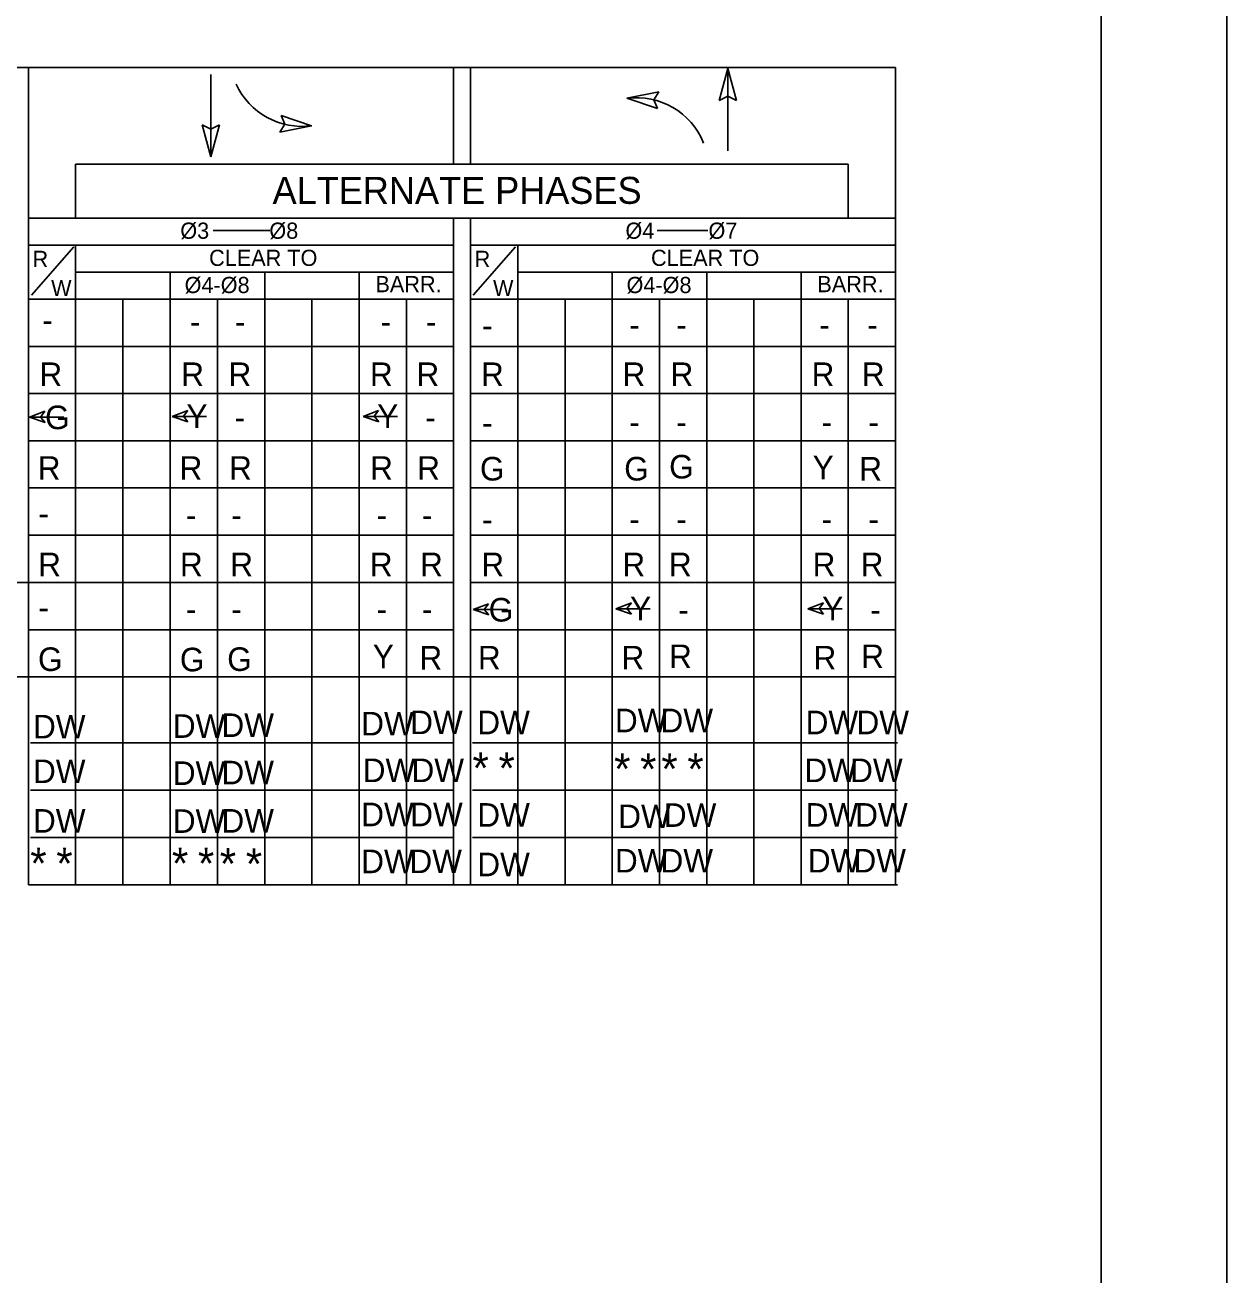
# Model space of a CAD drawing. Extents: x 0 to 3.01, y -0.05 to 1.83.
# Drawn here: x 2.6407 to 3, y 0.8925 to 1.2662 of the extents above; entities that cross this region are included whole.
import ezdxf

# ---------------------------------------------------------------- set-up
doc = ezdxf.new("R2010")
doc.units = 0
for name, color, linetype in [('RD_SHT_IplotShp', 7, 'Continuous'), ('TR_TS_Border', 7, 'Continuous'), ('TR_TS_Phase1', 7, 'Continuous'), ('TR_TS_Phase2', 7, 'Continuous'), ('TR_TS_Phase3', 7, 'Continuous'), ('TR_TS_Phase4', 7, 'Continuous'), ('TR_TS_Phase5', 7, 'Continuous'), ('TR_TS_Phase6', 7, 'Continuous'), ('TR_TS_Phase7', 7, 'Continuous'), ('TR_TS_Phase8', 7, 'Continuous')]:
    doc.layers.add(name, color=color, linetype=linetype)

msp = doc.modelspace()

# ---------------------------------------------------------------- linework, layer by layer
at = {"layer": 'RD_SHT_IplotShp'}
msp.add_lwpolyline([(-3.9736429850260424e-10, -8.265177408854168e-09), (3.0000020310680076, -8.265177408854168e-09), (3.0000020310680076, 1.8333311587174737), (-3.9736429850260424e-10, 1.8333311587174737)], close=True, dxfattribs=at)
at = {"layer": 'TR_TS_Border'}
for p, q in [((3.0000020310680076, -8.265177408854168e-09), (3.0000020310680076, 1.8333311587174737)), ((2.9623464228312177, 0.04746643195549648), (2.9623464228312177, 1.775395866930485)), ((2.900956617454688, 1.2534462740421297), (2.372526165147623, 1.2534462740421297)), ((2.6418031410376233, 1.009138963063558), (2.6418031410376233, 1.2534462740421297)), ((2.7688228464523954, 1.2534461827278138), (2.7688228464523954, 1.2245734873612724)), ((2.7738845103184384, 1.2534461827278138), (2.7738845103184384, 1.2245734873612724)), ((2.900956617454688, 1.2534462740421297), (2.900956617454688, 1.009138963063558)), ((2.886825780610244, 1.2245736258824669), (2.6558814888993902, 1.2245736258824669)), ((2.6558814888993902, 1.2245736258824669), (2.6558814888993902, 1.2084390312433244)), ((2.886825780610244, 1.2245736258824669), (2.886825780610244, 1.2084390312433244)), ((2.768822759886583, 1.2084390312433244), (2.6418031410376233, 1.2084390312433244)), ((2.768822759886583, 1.2084390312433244), (2.773884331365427, 1.2084390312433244)), ((2.7688228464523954, 1.2084389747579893), (2.7688228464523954, 1.0091388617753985)), ((2.900956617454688, 1.2084390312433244), (2.773884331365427, 1.2084390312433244)), ((2.7738845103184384, 1.2084389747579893), (2.7738845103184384, 1.0091388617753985)), ((2.696972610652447, 1.2046953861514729), (2.7138807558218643, 1.2046953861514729)), ((2.829719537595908, 1.2046953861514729), (2.844828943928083, 1.2046953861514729)), ((2.6418031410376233, 1.2003716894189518), (2.768822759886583, 1.2003716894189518)), ((2.6426469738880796, 1.185449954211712), (2.6553012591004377, 1.1998447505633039)), ((2.6558814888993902, 1.2003716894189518), (2.6558814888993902, 1.009138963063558)), ((2.773884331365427, 1.2003716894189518), (2.900956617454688, 1.2003716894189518)), ((2.774728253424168, 1.185449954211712), (2.787382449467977, 1.1998447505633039)), ((2.7880152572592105, 1.2003716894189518), (2.7880152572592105, 1.009138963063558)), ((2.6558814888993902, 1.192304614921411), (2.768822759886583, 1.192304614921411)), ((2.6841428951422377, 1.192304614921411), (2.6841428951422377, 1.009138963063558)), ((2.712404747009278, 1.192304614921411), (2.712404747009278, 1.009138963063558)), ((2.7406138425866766, 1.192304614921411), (2.7406138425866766, 1.009138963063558)), ((2.7880152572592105, 1.192304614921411), (2.900956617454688, 1.192304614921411)), ((2.8162241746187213, 1.192304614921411), (2.8162241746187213, 1.009138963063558)), ((2.8444860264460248, 1.192304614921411), (2.8444860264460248, 1.009138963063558)), ((2.872695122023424, 1.192304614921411), (2.872695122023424, 1.009138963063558)), ((2.768822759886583, 1.1842374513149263), (2.6418031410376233, 1.1842374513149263)), ((2.67001232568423, 1.1842374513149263), (2.67001232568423, 1.009138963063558)), ((2.6982737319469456, 1.1842374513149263), (2.6982737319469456, 1.009138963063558)), ((2.7264830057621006, 1.1842374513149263), (2.7264830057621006, 1.009138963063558)), ((2.7547445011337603, 1.1842374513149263), (2.7547445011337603, 1.009138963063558)), ((2.900956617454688, 1.1842374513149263), (2.773884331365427, 1.1842374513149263)), ((2.802146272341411, 1.1842374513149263), (2.802146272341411, 1.009138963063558)), ((2.8303550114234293, 1.1842374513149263), (2.8303550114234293, 1.009138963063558)), ((2.8586168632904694, 1.1842374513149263), (2.8586168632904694, 1.009138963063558)), ((2.886825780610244, 1.1842374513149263), (2.886825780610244, 1.009138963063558)), ((2.768822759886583, 1.1701066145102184), (2.6418031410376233, 1.1701066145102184)), ((2.900956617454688, 1.1701066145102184), (2.773884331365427, 1.1701066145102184)), ((2.768822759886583, 1.155975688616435), (2.6418031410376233, 1.155975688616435)), ((2.900956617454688, 1.155975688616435), (2.773884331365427, 1.155975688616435)), ((2.768822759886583, 1.1418975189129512), (2.6418031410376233, 1.1418975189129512)), ((2.900956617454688, 1.1418975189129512), (2.773884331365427, 1.1418975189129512)), ((2.768822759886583, 1.1277666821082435), (2.6418031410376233, 1.1277666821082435)), ((2.900956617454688, 1.1277666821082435), (2.773884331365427, 1.1277666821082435)), ((2.768822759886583, 1.113635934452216), (2.6418031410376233, 1.113635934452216)), ((2.900956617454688, 1.113635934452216), (2.773884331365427, 1.113635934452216)), ((2.6317323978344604, 1.099505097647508), (2.6418031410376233, 1.099505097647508)), ((2.768822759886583, 1.099505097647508), (2.6418031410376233, 1.099505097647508)), ((2.6418031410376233, 1.099505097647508), (2.6418031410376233, 1.0712960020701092)), ((2.900956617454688, 1.099505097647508), (2.773884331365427, 1.099505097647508)), ((2.768822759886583, 1.085374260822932), (2.6418031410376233, 1.085374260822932)), ((2.900956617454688, 1.085374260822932), (2.773884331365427, 1.085374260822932)), ((2.6418031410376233, 1.0712960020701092), (2.6317323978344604, 1.0712960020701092)), ((2.768822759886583, 1.0712960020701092), (2.6418031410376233, 1.0712960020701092)), ((2.768822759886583, 1.0712960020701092), (2.773884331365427, 1.0712960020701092)), ((2.900956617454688, 1.0712960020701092), (2.773884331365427, 1.0712960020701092)), ((2.768822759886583, 1.05153174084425), (2.6423805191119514, 1.05153174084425)), ((2.9015339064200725, 1.05153174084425), (2.774461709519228, 1.05153174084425)), ((2.768822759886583, 1.037400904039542), (2.6423805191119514, 1.037400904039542)), ((2.9015339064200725, 1.037400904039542), (2.774461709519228, 1.037400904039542)), ((2.768822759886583, 1.0232697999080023), (2.6423805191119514, 1.0232697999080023)), ((2.9015339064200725, 1.0232697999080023), (2.774461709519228, 1.0232697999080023)), ((2.7694001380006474, 1.009138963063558), (2.6418031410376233, 1.009138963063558)), ((2.7694001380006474, 1.009138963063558), (2.774461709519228, 1.009138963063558)), ((2.9015339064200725, 1.009138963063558), (2.774461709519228, 1.009138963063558))]:
    msp.add_line(p, q, dxfattribs=at)
at = {"layer": 'TR_TS_Phase3'}
for p, q in [((2.718364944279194, 1.2365514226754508), (2.717261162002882, 1.2391357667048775)), ((2.717261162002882, 1.2391357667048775), (2.7264059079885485, 1.2359971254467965)), ((2.7168954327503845, 1.2341504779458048), (2.718364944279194, 1.2365514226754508)), ((2.7264059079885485, 1.2359971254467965), (2.7168954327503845, 1.2341504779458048)), ((2.642075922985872, 1.1489186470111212), (2.6467103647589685, 1.1506814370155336)), ((2.652337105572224, 1.1489186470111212), (2.642075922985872, 1.1489186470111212)), ((2.646754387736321, 1.147310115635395), (2.642075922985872, 1.1489186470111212)), ((2.6467103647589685, 1.1506814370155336), (2.6453810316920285, 1.1489773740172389)), ((2.6453810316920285, 1.1489773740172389), (2.646754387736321, 1.147310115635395)), ((2.6847727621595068, 1.149179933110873), (2.689407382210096, 1.1509425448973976)), ((2.6950340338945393, 1.149179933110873), (2.6847727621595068, 1.149179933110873)), ((2.68945140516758, 1.1475714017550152), (2.6847727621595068, 1.149179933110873)), ((2.689407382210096, 1.1509425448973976), (2.6880778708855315, 1.1492386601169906)), ((2.6880778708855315, 1.1492386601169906), (2.68945140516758, 1.1475714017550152)), ((2.74178080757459, 1.149179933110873), (2.7464152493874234, 1.1509425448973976)), ((2.7520419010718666, 1.149179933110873), (2.74178080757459, 1.149179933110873)), ((2.7464594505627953, 1.1475714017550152), (2.74178080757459, 1.149179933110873)), ((2.7464152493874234, 1.1509425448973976), (2.74508591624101, 1.1492386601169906)), ((2.74508591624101, 1.1492386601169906), (2.7464594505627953, 1.1475714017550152))]:
    msp.add_line(p, q, dxfattribs=at)
msp.add_arc((2.7235502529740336, 1.2574811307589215), 0.021617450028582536, 204.5246166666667, 277.6927888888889, dxfattribs=at)
at = {"layer": 'TR_TS_Phase4'}
for p, q in [((2.850787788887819, 1.253204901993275), (2.8481964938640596, 1.2435802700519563)), ((2.850787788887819, 1.253204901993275), (2.850787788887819, 1.228584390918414)), ((2.8533789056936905, 1.2435802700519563), (2.850787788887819, 1.253204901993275)), ((2.8481964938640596, 1.2435802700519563), (2.850787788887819, 1.2449129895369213)), ((2.850787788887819, 1.2449129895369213), (2.8533789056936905, 1.2435802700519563))]:
    msp.add_line(p, q, dxfattribs=at)
at = {"layer": 'TR_TS_Phase7'}
for p, q in [((2.820663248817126, 1.2443299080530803), (2.830173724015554, 1.2461762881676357)), ((2.830173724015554, 1.2461762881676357), (2.8287042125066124, 1.243775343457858)), ((2.8298079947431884, 1.2411911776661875), (2.820663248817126, 1.2443299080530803)), ((2.8287042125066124, 1.243775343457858), (2.8298079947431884, 1.2411911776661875)), ((2.774661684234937, 1.0914069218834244), (2.7792963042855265, 1.0931695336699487)), ((2.784923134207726, 1.0914069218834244), (2.774661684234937, 1.0914069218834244)), ((2.7793403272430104, 1.08979839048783), (2.774661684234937, 1.0914069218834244)), ((2.7792963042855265, 1.0931695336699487), (2.777966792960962, 1.0914656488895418)), ((2.777966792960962, 1.0914656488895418), (2.7793403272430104, 1.08979839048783)), ((2.817358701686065, 1.091667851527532), (2.8219933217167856, 1.0934304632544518)), ((2.8276199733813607, 1.091667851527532), (2.817358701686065, 1.091667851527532)), ((2.822037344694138, 1.0900593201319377), (2.817358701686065, 1.091667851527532)), ((2.8219933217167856, 1.0934304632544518), (2.820663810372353, 1.0917265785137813)), ((2.820663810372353, 1.0917265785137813), (2.822037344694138, 1.0900593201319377)), ((2.87476687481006, 1.091667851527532), (2.8794014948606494, 1.0934304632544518)), ((2.8850279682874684, 1.091667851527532), (2.87476687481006, 1.091667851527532)), ((2.8794455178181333, 1.0900593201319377), (2.87476687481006, 1.091667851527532)), ((2.8794014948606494, 1.0934304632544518), (2.878071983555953, 1.0917265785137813)), ((2.878071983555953, 1.0917265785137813), (2.8794455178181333, 1.0900593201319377))]:
    msp.add_line(p, q, dxfattribs=at)
msp.add_arc((2.823518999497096, 1.2228452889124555), 0.021617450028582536, 21.869405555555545, 97.69278888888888, dxfattribs=at)
at = {"layer": 'TR_TS_Phase8'}
for p, q in [((2.6962813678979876, 1.2267372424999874), (2.6962813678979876, 1.2513575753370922)), ((2.6962813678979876, 1.2350288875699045), (2.693690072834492, 1.2363616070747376)), ((2.693690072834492, 1.2363616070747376), (2.6962813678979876, 1.2267372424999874)), ((2.698872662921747, 1.2363616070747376), (2.6962813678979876, 1.2350288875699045)), ((2.6962813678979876, 1.2267372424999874), (2.698872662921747, 1.2363616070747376))]:
    msp.add_line(p, q, dxfattribs=at)

# ---------------------------------------------------------------- texts
at = {"layer": 'TR_TS_Border'}
for s, height, p in [('ALTERNATE PHASES', 0.00806692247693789, (2.7147410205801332, 1.212709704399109)), ('Ø3          Ø8', 0.004840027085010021, (2.687162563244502, 1.202269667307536)), ('Ø4         Ø7', 0.004840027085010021, (2.820207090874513, 1.202269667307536)), ('R', 0.004840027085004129, (2.6430010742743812, 1.1938336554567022)), ('CLEAR TO', 0.004840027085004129, (2.6957715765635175, 1.1941499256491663)), ('R', 0.004840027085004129, (2.7751351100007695, 1.1938336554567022)), ('CLEAR TO', 0.004840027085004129, (2.827852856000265, 1.1941499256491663)), ('W', 0.004840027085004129, (2.6485480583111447, 1.1851340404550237)), ('Ø4-Ø8', 0.004840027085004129, (2.688454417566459, 1.186030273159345)), ('BARR.', 0.004840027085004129, (2.745489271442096, 1.186293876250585)), ('W', 0.004840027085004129, (2.780629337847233, 1.1851340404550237)), ('Ø4-Ø8', 0.004840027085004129, (2.82053560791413, 1.186030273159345)), ('BARR.', 0.004840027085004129, (2.877570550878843, 1.186293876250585))]:
    msp.add_text(s, height=height, rotation=360, dxfattribs=at).set_placement(p)
at = {"layer": 'TR_TS_Phase1'}
for p in [(2.645924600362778, 1.1744686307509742), (2.6900332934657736, 1.1739495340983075), (2.7035251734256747, 1.1739495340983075), (2.7470411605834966, 1.1739495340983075), (2.76053321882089, 1.1739495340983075), (2.7773641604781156, 1.172916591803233), (2.821382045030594, 1.1730729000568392), (2.835416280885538, 1.1730729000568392), (2.8781681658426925, 1.1730729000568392), (2.8925133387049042, 1.1730729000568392)]:
    msp.add_text('-', height=0.007050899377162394, dxfattribs=at).set_placement(p)
at = {"layer": 'TR_TS_Phase2'}
for p in [(2.64505608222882, 1.1582365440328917), (2.6874429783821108, 1.1582365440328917), (2.7015719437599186, 1.1582365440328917), (2.743845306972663, 1.1582365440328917), (2.757749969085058, 1.1582365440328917), (2.7770371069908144, 1.1582365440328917), (2.8193315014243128, 1.1582365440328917), (2.8336848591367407, 1.1582365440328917), (2.875847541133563, 1.1582365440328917), (2.890873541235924, 1.1582365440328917)]:
    msp.add_text('R', height=0.007050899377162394, rotation=360, dxfattribs=at).set_placement(p)
for p in [(2.8170630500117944, 1.0547270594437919), (2.8306928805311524, 1.0547270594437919), (2.6431330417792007, 1.052876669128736), (2.6849198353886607, 1.053052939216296), (2.6994478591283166, 1.0533047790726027), (2.741234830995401, 1.0537693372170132), (2.7558768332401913, 1.0541542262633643), (2.775932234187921, 1.0541259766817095), (2.874065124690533, 1.0541259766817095), (2.889252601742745, 1.0541259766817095)]:
    msp.add_text('DW', height=0.007050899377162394, dxfattribs=at).set_placement(p)
at = {"layer": 'TR_TS_Phase3'}
for s, p in [('G', (2.646752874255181, 1.145338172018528)), ('Y', (2.689002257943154, 1.1456915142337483)), ('Y', (2.7460103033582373, 1.1456915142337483)), ('-', (2.703372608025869, 1.145338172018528)), ('-', (2.760380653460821, 1.145338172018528)), ('-', (2.7773641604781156, 1.1437956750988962)), ('-', (2.821382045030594, 1.1439520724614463)), ('-', (2.835416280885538, 1.1439520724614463)), ('-', (2.87879021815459, 1.1439520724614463)), ('-', (2.892824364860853, 1.1439520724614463))]:
    msp.add_text(s, height=0.007050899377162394, dxfattribs=at).set_placement(p)
at = {"layer": 'TR_TS_Phase4'}
for s, height, p in [('R', 0.007050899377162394, (2.6445564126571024, 1.1302016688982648)), ('R', 0.007050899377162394, (2.6869433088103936, 1.1302016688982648)), ('R', 0.007050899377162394, (2.701745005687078, 1.1302016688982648)), ('R', 0.007050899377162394, (2.7439077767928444, 1.1302016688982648)), ('R', 0.007050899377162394, (2.7579548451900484, 1.1302016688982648)), ('G', 0.007050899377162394, (2.7767327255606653, 1.1299915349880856)), ('G', 0.007050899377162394, (2.8198378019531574, 1.1299915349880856)), ('G', 0.007050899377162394, (2.8332705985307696, 1.1305931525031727)), ('DW', 0.007050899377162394, (2.6431330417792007, 1.0395282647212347)), ('DW', 0.007050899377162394, (2.7416840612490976, 1.0398178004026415)), ('DW', 0.007050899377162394, (2.756261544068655, 1.0398178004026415)), ('*', 0.009384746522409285, (2.7744891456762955, 1.0393489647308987)), ('*', 0.009384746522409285, (2.7822597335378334, 1.0392927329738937)), ('*', 0.009384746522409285, (2.8168236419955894, 1.0390825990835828)), ('*', 0.009384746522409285, (2.8245942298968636, 1.0390261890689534)), ('*', 0.009384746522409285, (2.8309352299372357, 1.0390825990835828)), ('*', 0.009384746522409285, (2.8387058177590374, 1.0390261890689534)), ('DW', 0.007050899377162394, (2.873688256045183, 1.0398178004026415)), ('DW', 0.007050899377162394, (2.8873687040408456, 1.0398178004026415)), ('DW', 0.007050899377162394, (2.6849198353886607, 1.03896710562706)), ('DW', 0.007050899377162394, (2.6994478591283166, 1.0391546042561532))]:
    msp.add_text(s, height=height, dxfattribs=at).set_placement(p)
for s, p in [('Y', (2.876168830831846, 1.130357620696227)), ('R', (2.890087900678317, 1.1299839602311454))]:
    msp.add_text(s, height=0.007050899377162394, rotation=360, dxfattribs=at).set_placement(p)
at = {"layer": 'TR_TS_Phase5'}
for p in [(2.644754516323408, 1.116682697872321), (2.688863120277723, 1.116163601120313), (2.7023550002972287, 1.116163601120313), (2.745870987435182, 1.116163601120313), (2.7593630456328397, 1.116163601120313), (2.7773641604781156, 1.11482651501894), (2.821382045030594, 1.114982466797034), (2.835416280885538, 1.114982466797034), (2.87879021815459, 1.114982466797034), (2.892824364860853, 1.114982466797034)]:
    msp.add_text('-', height=0.007050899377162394, dxfattribs=at).set_placement(p)
at = {"layer": 'TR_TS_Phase6'}
for s, p in [('R', (2.6446761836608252, 1.1013816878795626)), ('R', (2.6870629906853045, 1.1013816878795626)), ('R', (2.7020890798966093, 1.1013816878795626)), ('R', (2.7438031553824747, 1.1013816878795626)), ('R', (2.758829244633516, 1.1013816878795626)), ('R', (2.777130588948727, 1.1013816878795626)), ('R', (2.819293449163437, 1.1013816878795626)), ('R', (2.833198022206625, 1.1013816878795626)), ('R', (2.876151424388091, 1.1013816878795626)), ('R', (2.890504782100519, 1.1013816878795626)), ('DW', (2.6431330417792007, 1.024701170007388)), ('DW', (2.6849198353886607, 1.0246530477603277)), ('DW', (2.6994478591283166, 1.0247126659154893)), ('DW', (2.741234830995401, 1.0266200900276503)), ('DW', (2.7558768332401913, 1.0266200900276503)), ('DW', (2.775932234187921, 1.0264801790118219)), ('DW', (2.8180488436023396, 1.0260594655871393)), ('DW', (2.831678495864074, 1.0264442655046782)), ('DW', (2.874065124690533, 1.0264801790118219)), ('DW', (2.8888629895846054, 1.0264801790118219))]:
    msp.add_text(s, height=0.007050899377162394, dxfattribs=at).set_placement(p)
at = {"layer": 'TR_TS_Phase7'}
for s, p in [('Y', (2.821588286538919, 1.088179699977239)), ('Y', (2.878996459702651, 1.088179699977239)), ('-', (2.644754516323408, 1.0885706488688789)), ('G', (2.7793389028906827, 1.087826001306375)), ('-', (2.688863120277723, 1.0880515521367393)), ('-', (2.7023550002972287, 1.0880515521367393)), ('-', (2.745870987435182, 1.0880515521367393)), ('-', (2.7593630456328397, 1.0880515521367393)), ('-', (2.8359585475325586, 1.087826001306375)), ('-', (2.8933667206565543, 1.087826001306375))]:
    msp.add_text(s, height=0.007050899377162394, dxfattribs=at).set_placement(p)
at = {"layer": 'TR_TS_Phase8'}
for s, height, p in [('G', 0.007050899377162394, (2.644632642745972, 1.0730398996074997)), ('G', 0.007050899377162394, (2.687043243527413, 1.0729449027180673)), ('G', 0.007050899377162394, (2.7011800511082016, 1.073057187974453)), ('R', 0.007050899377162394, (2.776118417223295, 1.073492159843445)), ('R', 0.007050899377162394, (2.819022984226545, 1.073492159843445)), ('R', 0.007050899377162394, (2.833257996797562, 1.0738934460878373)), ('R', 0.007050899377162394, (2.8764311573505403, 1.073492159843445)), ('R', 0.007050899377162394, (2.8906661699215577, 1.0738934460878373)), ('*', 0.009384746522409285, (2.642329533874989, 1.0108548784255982)), ('*', 0.009384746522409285, (2.650100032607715, 1.0107987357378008)), ('*', 0.009384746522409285, (2.6846642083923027, 1.0108548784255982)), ('*', 0.009384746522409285, (2.6924347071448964, 1.0107987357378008)), ('*', 0.009384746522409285, (2.69897015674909, 1.0107318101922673)), ('*', 0.009384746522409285, (2.70674065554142, 1.0106755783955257)), ('DW', 0.007050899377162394, (2.7412404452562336, 1.0125895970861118)), ('DW', 0.007050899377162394, (2.7556391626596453, 1.0126089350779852)), ('DW', 0.007050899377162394, (2.775932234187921, 1.0116830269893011)), ('DW', 0.007050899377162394, (2.8170630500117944, 1.012801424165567)), ('DW', 0.007050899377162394, (2.8306928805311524, 1.012801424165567)), ('DW', 0.007050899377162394, (2.874727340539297, 1.012801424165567)), ('DW', 0.007050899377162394, (2.8883569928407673, 1.012801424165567))]:
    msp.add_text(s, height=height, dxfattribs=at).set_placement(p)
for s, p in [('Y', (2.744701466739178, 1.0738522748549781)), ('R', (2.758620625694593, 1.0734786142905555))]:
    msp.add_text(s, height=0.007050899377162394, rotation=360, dxfattribs=at).set_placement(p)

doc.saveas('drawing.dxf')
